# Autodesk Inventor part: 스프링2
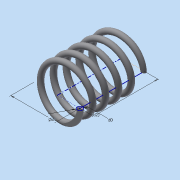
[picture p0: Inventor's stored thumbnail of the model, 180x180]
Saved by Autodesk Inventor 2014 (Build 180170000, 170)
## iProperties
Created: 2016-01
Part Number: 스프링2
Material: 강철, 탄소
Document SubType Name: Modeling
Designer: Administrator
Density: 7.87 g/cm^3
Appearance: 반연마
Mass: 6.44239 g
Surface Area: 16.6857 cm^2
Volume: 0.818602 cm^3
Author: Administrator
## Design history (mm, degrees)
sketch "스케치1"
  geometry: L1 (0, 0)-(0, 17.5); L2 (0, 17.5)-(8.5, 17.5); L3 (8.5, 17.5)-(8.5, 0); L4 (8.5, 0)-(0, 0); C1 r 1 at (8.5, 0)
  constraints: 8 end point, 2 parallel, 1 centre point, 1 coincident, 1 perpendicular, 1 vertical
  dimensions: "d0" = 2 diameter of C1; "d1" = 17 diameter of L3 L1; "d2" = 17.5 distance between parallel lines of L4 L2 (derived)
feature "코일1" pitch "d3" = 10; turns "d5" = 5; dims "d4" = 17.5 (= d2), "d6" = 0, angle "d7" = 90 deg, angle "d8" = 90 deg, "d9" = 0, "d10" = 0
node "작업 평면1"
sketch "스케치2"
  geometry: L1 (-9.5, 0)-(-7.5, 0) reference; L2 (-9.5, 0)-(-7.5, 0) reference; 1 further point
  constraints: 2 horizontal alignment
extrude "돌출1" cut sketch "스케치2" distance "d12" = 10; taper "d13" = 0 deg
node "작업 평면2"
sketch "스케치3"
  geometry: L1 (-7.5, 0)-(-9.5, 0) reference; 1 further point
  constraints: 1 horizontal alignment
extrude "돌출2" cut sketch "스케치3" distance "d15" = 10; taper "d16" = 0 deg
node "솔리드1"
node "절단 모서리 투영1"
node "절단 모서리 투영2"
node "절단 모서리 투영3"
other parameters: "d11" = 0, "d14" = 17.5 (= d2)
